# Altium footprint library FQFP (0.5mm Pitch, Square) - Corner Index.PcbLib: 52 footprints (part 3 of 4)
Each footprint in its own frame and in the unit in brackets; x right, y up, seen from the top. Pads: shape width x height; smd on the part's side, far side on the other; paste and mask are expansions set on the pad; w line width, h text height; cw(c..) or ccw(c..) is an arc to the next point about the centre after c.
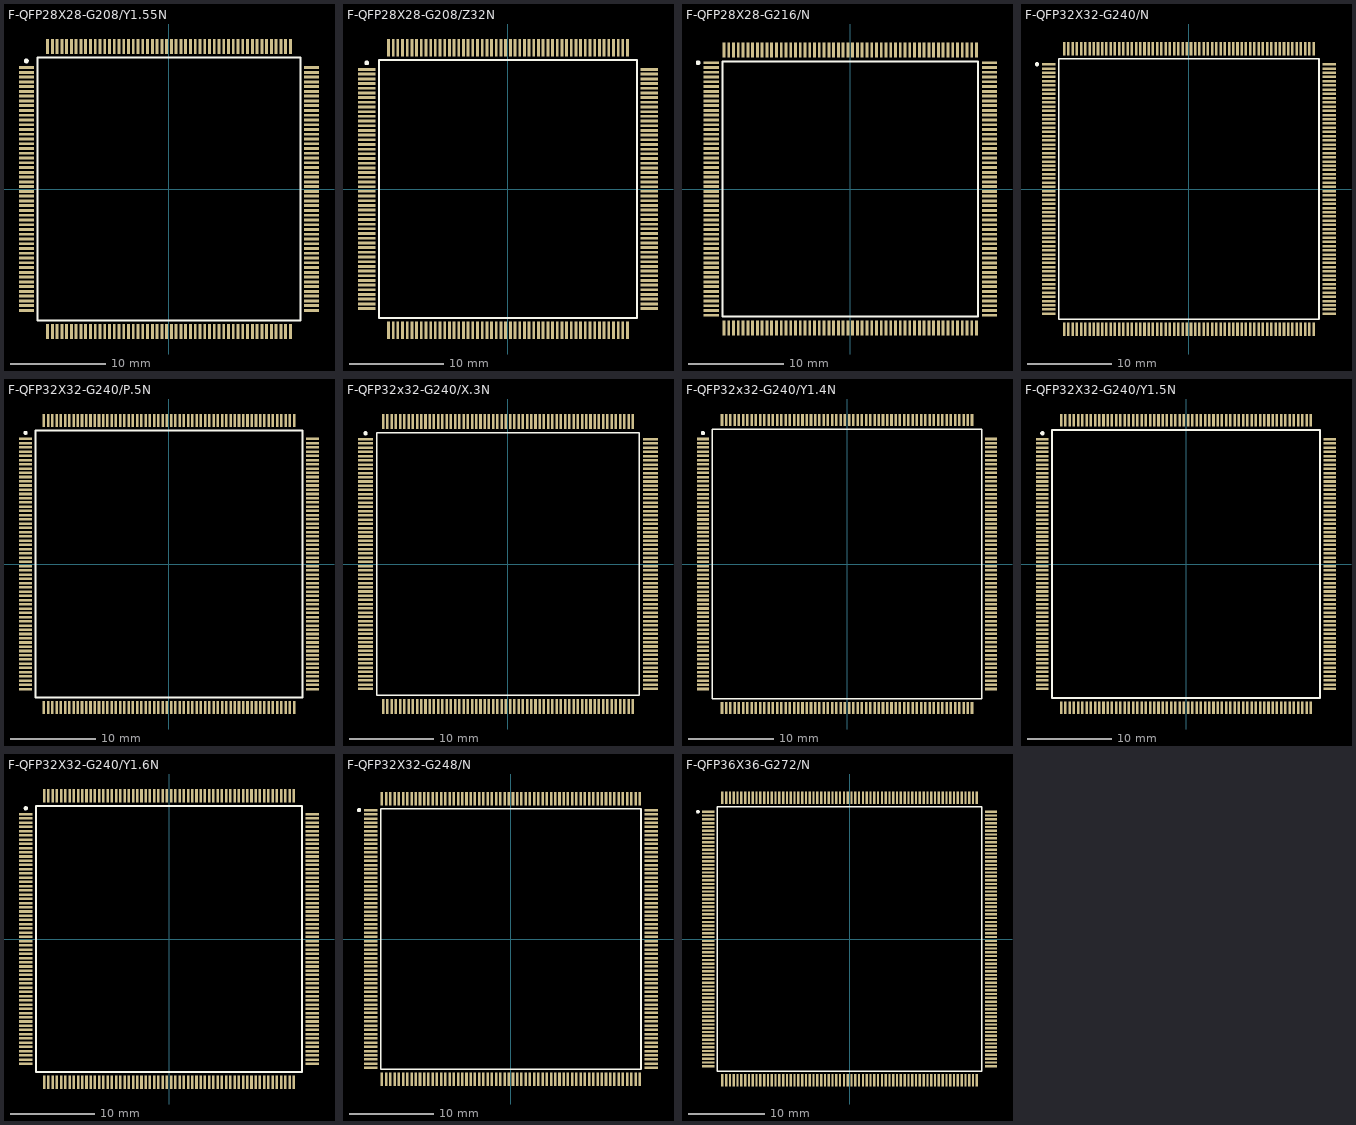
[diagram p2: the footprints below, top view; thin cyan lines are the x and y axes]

## F-QFP28X28-G208/Y1.55N [mm]
pads (208):
  rect 1.55x0.3 smd: 1(-14.975,12.75) 2(-14.975,12.25) 3(-14.975,11.75) 4(-14.975,11.25) 5(-14.975,10.75) 6(-14.975,10.25) 7(-14.975,9.75) 8(-14.975,9.25) 9(-14.975,8.75) 10(-14.975,8.25) 11(-14.975,7.75) 12(-14.975,7.25) 13(-14.975,6.75) 14(-14.975,6.25) 15(-14.975,5.75) 16(-14.975,5.25) 17(-14.975,4.75) 18(-14.975,4.25) 19(-14.975,3.75) 20(-14.975,3.25) 21(-14.975,2.75) 22(-14.975,2.25) 23(-14.975,1.75) 24(-14.975,1.25) 25(-14.975,0.75) 26(-14.975,0.25) 27(-14.975,-0.25) 28(-14.975,-0.75) 29(-14.975,-1.25) 30(-14.975,-1.75) 31(-14.975,-2.25) 32(-14.975,-2.75) 33(-14.975,-3.25) 34(-14.975,-3.75) 35(-14.975,-4.25) 36(-14.975,-4.75) 37(-14.975,-5.25) 38(-14.975,-5.75) 39(-14.975,-6.25) 40(-14.975,-6.75) 41(-14.975,-7.25) 42(-14.975,-7.75) 43(-14.975,-8.25) 44(-14.975,-8.75) 45(-14.975,-9.25) 46(-14.975,-9.75) 47(-14.975,-10.25) 48(-14.975,-10.75) 49(-14.975,-11.25) 50(-14.975,-11.75) 51(-14.975,-12.25) 52(-14.975,-12.75) 105(14.975,-12.75) 106(14.975,-12.25) 107(14.975,-11.75) 108(14.975,-11.25) 109(14.975,-10.75) 110(14.975,-10.25) 111(14.975,-9.75) 112(14.975,-9.25) 113(14.975,-8.75) 114(14.975,-8.25) 115(14.975,-7.75) 116(14.975,-7.25) 117(14.975,-6.75) 118(14.975,-6.25) 119(14.975,-5.75) 120(14.975,-5.25) 121(14.975,-4.75) 122(14.975,-4.25) 123(14.975,-3.75) 124(14.975,-3.25) 125(14.975,-2.75) 126(14.975,-2.25) 127(14.975,-1.75) 128(14.975,-1.25) 129(14.975,-0.75) 130(14.975,-0.25) 131(14.975,0.25) 132(14.975,0.75) 133(14.975,1.25) 134(14.975,1.75) 135(14.975,2.25) 136(14.975,2.75) 137(14.975,3.25) 138(14.975,3.75) 139(14.975,4.25) 140(14.975,4.75) 141(14.975,5.25) 142(14.975,5.75) 143(14.975,6.25) 144(14.975,6.75) 145(14.975,7.25) 146(14.975,7.75) 147(14.975,8.25) 148(14.975,8.75) 149(14.975,9.25) 150(14.975,9.75) 151(14.975,10.25) 152(14.975,10.75) 153(14.975,11.25) 154(14.975,11.75) 155(14.975,12.25) 156(14.975,12.75)
  rect 0.3x1.55 smd: 53(-12.75,-14.975) 54(-12.25,-14.975) 55(-11.75,-14.975) 56(-11.25,-14.975) 57(-10.75,-14.975) 58(-10.25,-14.975) 59(-9.75,-14.975) 60(-9.25,-14.975) 61(-8.75,-14.975) 62(-8.25,-14.975) 63(-7.75,-14.975) 64(-7.25,-14.975) 65(-6.75,-14.975) 66(-6.25,-14.975) 67(-5.75,-14.975) 68(-5.25,-14.975) 69(-4.75,-14.975) 70(-4.25,-14.975) 71(-3.75,-14.975) 72(-3.25,-14.975) 73(-2.75,-14.975) 74(-2.25,-14.975) 75(-1.75,-14.975) 76(-1.25,-14.975) 77(-0.75,-14.975) 78(-0.25,-14.975) 79(0.25,-14.975) 80(0.75,-14.975) 81(1.25,-14.975) 82(1.75,-14.975) 83(2.25,-14.975) 84(2.75,-14.975) 85(3.25,-14.975) 86(3.75,-14.975) 87(4.25,-14.975) 88(4.75,-14.975) 89(5.25,-14.975) 90(5.75,-14.975) 91(6.25,-14.975) 92(6.75,-14.975) 93(7.25,-14.975) 94(7.75,-14.975) 95(8.25,-14.975) 96(8.75,-14.975) 97(9.25,-14.975) 98(9.75,-14.975) 99(10.25,-14.975) 100(10.75,-14.975) 101(11.25,-14.975) 102(11.75,-14.975) 103(12.25,-14.975) 104(12.75,-14.975) 157(12.75,14.975) 158(12.25,14.975) 159(11.75,14.975) 160(11.25,14.975) 161(10.75,14.975) 162(10.25,14.975) 163(9.75,14.975) 164(9.25,14.975) 165(8.75,14.975) 166(8.25,14.975) 167(7.75,14.975) 168(7.25,14.975) 169(6.75,14.975) 170(6.25,14.975) 171(5.75,14.975) 172(5.25,14.975) 173(4.75,14.975) 174(4.25,14.975) 175(3.75,14.975) 176(3.25,14.975) 177(2.75,14.975) 178(2.25,14.975) 179(1.75,14.975) 180(1.25,14.975) 181(0.75,14.975) 182(0.25,14.975) 183(-0.25,14.975) 184(-0.75,14.975) 185(-1.25,14.975) 186(-1.75,14.975) 187(-2.25,14.975) 188(-2.75,14.975) 189(-3.25,14.975) 190(-3.75,14.975) 191(-4.25,14.975) 192(-4.75,14.975) 193(-5.25,14.975) 194(-5.75,14.975) 195(-6.25,14.975) 196(-6.75,14.975) 197(-7.25,14.975) 198(-7.75,14.975) 199(-8.25,14.975) 200(-8.75,14.975) 201(-9.25,14.975) 202(-9.75,14.975) 203(-10.25,14.975) 204(-10.75,14.975) 205(-11.25,14.975) 206(-11.75,14.975) 207(-12.25,14.975) 208(-12.75,14.975)
Top Overlay:
  circle w0.25: c-14.975,13.45 r0.125
  lines w0.2: -13.8,-13.8 -13.8,13.8 13.8,13.8 13.8,-13.8 -13.8,-13.8

## F-QFP28X28-G208/Z32N [mm]
pads (208):
  rect 1.85x0.3 smd: 1(-15.075,12.75) 2(-15.075,12.25) 3(-15.075,11.75) 4(-15.075,11.25) 5(-15.075,10.75) 6(-15.075,10.25) 7(-15.075,9.75) 8(-15.075,9.25) 9(-15.075,8.75) 10(-15.075,8.25) 11(-15.075,7.75) 12(-15.075,7.25) 13(-15.075,6.75) 14(-15.075,6.25) 15(-15.075,5.75) 16(-15.075,5.25) 17(-15.075,4.75) 18(-15.075,4.25) 19(-15.075,3.75) 20(-15.075,3.25) 21(-15.075,2.75) 22(-15.075,2.25) 23(-15.075,1.75) 24(-15.075,1.25) 25(-15.075,0.75) 26(-15.075,0.25) 27(-15.075,-0.25) 28(-15.075,-0.75) 29(-15.075,-1.25) 30(-15.075,-1.75) 31(-15.075,-2.25) 32(-15.075,-2.75) 33(-15.075,-3.25) 34(-15.075,-3.75) 35(-15.075,-4.25) 36(-15.075,-4.75) 37(-15.075,-5.25) 38(-15.075,-5.75) 39(-15.075,-6.25) 40(-15.075,-6.75) 41(-15.075,-7.25) 42(-15.075,-7.75) 43(-15.075,-8.25) 44(-15.075,-8.75) 45(-15.075,-9.25) 46(-15.075,-9.75) 47(-15.075,-10.25) 48(-15.075,-10.75) 49(-15.075,-11.25) 50(-15.075,-11.75) 51(-15.075,-12.25) 52(-15.075,-12.75) 105(15.075,-12.75) 106(15.075,-12.25) 107(15.075,-11.75) 108(15.075,-11.25) 109(15.075,-10.75) 110(15.075,-10.25) 111(15.075,-9.75) 112(15.075,-9.25) 113(15.075,-8.75) 114(15.075,-8.25) 115(15.075,-7.75) 116(15.075,-7.25) 117(15.075,-6.75) 118(15.075,-6.25) 119(15.075,-5.75) 120(15.075,-5.25) 121(15.075,-4.75) 122(15.075,-4.25) 123(15.075,-3.75) 124(15.075,-3.25) 125(15.075,-2.75) 126(15.075,-2.25) 127(15.075,-1.75) 128(15.075,-1.25) 129(15.075,-0.75) 130(15.075,-0.25) 131(15.075,0.25) 132(15.075,0.75) 133(15.075,1.25) 134(15.075,1.75) 135(15.075,2.25) 136(15.075,2.75) 137(15.075,3.25) 138(15.075,3.75) 139(15.075,4.25) 140(15.075,4.75) 141(15.075,5.25) 142(15.075,5.75) 143(15.075,6.25) 144(15.075,6.75) 145(15.075,7.25) 146(15.075,7.75) 147(15.075,8.25) 148(15.075,8.75) 149(15.075,9.25) 150(15.075,9.75) 151(15.075,10.25) 152(15.075,10.75) 153(15.075,11.25) 154(15.075,11.75) 155(15.075,12.25) 156(15.075,12.75)
  rect 0.3x1.85 smd: 53(-12.75,-15.075) 54(-12.25,-15.075) 55(-11.75,-15.075) 56(-11.25,-15.075) 57(-10.75,-15.075) 58(-10.25,-15.075) 59(-9.75,-15.075) 60(-9.25,-15.075) 61(-8.75,-15.075) 62(-8.25,-15.075) 63(-7.75,-15.075) 64(-7.25,-15.075) 65(-6.75,-15.075) 66(-6.25,-15.075) 67(-5.75,-15.075) 68(-5.25,-15.075) 69(-4.75,-15.075) 70(-4.25,-15.075) 71(-3.75,-15.075) 72(-3.25,-15.075) 73(-2.75,-15.075) 74(-2.25,-15.075) 75(-1.75,-15.075) 76(-1.25,-15.075) 77(-0.75,-15.075) 78(-0.25,-15.075) 79(0.25,-15.075) 80(0.75,-15.075) 81(1.25,-15.075) 82(1.75,-15.075) 83(2.25,-15.075) 84(2.75,-15.075) 85(3.25,-15.075) 86(3.75,-15.075) 87(4.25,-15.075) 88(4.75,-15.075) 89(5.25,-15.075) 90(5.75,-15.075) 91(6.25,-15.075) 92(6.75,-15.075) 93(7.25,-15.075) 94(7.75,-15.075) 95(8.25,-15.075) 96(8.75,-15.075) 97(9.25,-15.075) 98(9.75,-15.075) 99(10.25,-15.075) 100(10.75,-15.075) 101(11.25,-15.075) 102(11.75,-15.075) 103(12.25,-15.075) 104(12.75,-15.075) 157(12.75,15.075) 158(12.25,15.075) 159(11.75,15.075) 160(11.25,15.075) 161(10.75,15.075) 162(10.25,15.075) 163(9.75,15.075) 164(9.25,15.075) 165(8.75,15.075) 166(8.25,15.075) 167(7.75,15.075) 168(7.25,15.075) 169(6.75,15.075) 170(6.25,15.075) 171(5.75,15.075) 172(5.25,15.075) 173(4.75,15.075) 174(4.25,15.075) 175(3.75,15.075) 176(3.25,15.075) 177(2.75,15.075) 178(2.25,15.075) 179(1.75,15.075) 180(1.25,15.075) 181(0.75,15.075) 182(0.25,15.075) 183(-0.25,15.075) 184(-0.75,15.075) 185(-1.25,15.075) 186(-1.75,15.075) 187(-2.25,15.075) 188(-2.75,15.075) 189(-3.25,15.075) 190(-3.75,15.075) 191(-4.25,15.075) 192(-4.75,15.075) 193(-5.25,15.075) 194(-5.75,15.075) 195(-6.25,15.075) 196(-6.75,15.075) 197(-7.25,15.075) 198(-7.75,15.075) 199(-8.25,15.075) 200(-8.75,15.075) 201(-9.25,15.075) 202(-9.75,15.075) 203(-10.25,15.075) 204(-10.75,15.075) 205(-11.25,15.075) 206(-11.75,15.075) 207(-12.25,15.075) 208(-12.75,15.075)
Top Overlay:
  circle w0.25: c-15.075,13.45 r0.125
  lines w0.2: -13.75,-13.75 13.75,-13.75 13.75,13.75 -13.75,13.75 -13.75,-13.75

## F-QFP28X28-G216/N [mm]
pads (216):
  rect 1.6x0.3 smd: 1(-14.6,13.25) 2(-14.6,12.75) 3(-14.6,12.25) 4(-14.6,11.75) 5(-14.6,11.25) 6(-14.6,10.75) 7(-14.6,10.25) 8(-14.6,9.75) 9(-14.6,9.25) 10(-14.6,8.75) 11(-14.6,8.25) 12(-14.6,7.75) 13(-14.6,7.25) 14(-14.6,6.75) 15(-14.6,6.25) 16(-14.6,5.75) 17(-14.6,5.25) 18(-14.6,4.75) 19(-14.6,4.25) 20(-14.6,3.75) 21(-14.6,3.25) 22(-14.6,2.75) 23(-14.6,2.25) 24(-14.6,1.75) 25(-14.6,1.25) 26(-14.6,0.75) 27(-14.6,0.25) 28(-14.6,-0.25) 29(-14.6,-0.75) 30(-14.6,-1.25) 31(-14.6,-1.75) 32(-14.6,-2.25) 33(-14.6,-2.75) 34(-14.6,-3.25) 35(-14.6,-3.75) 36(-14.6,-4.25) 37(-14.6,-4.75) 38(-14.6,-5.25) 39(-14.6,-5.75) 40(-14.6,-6.25) 41(-14.6,-6.75) 42(-14.6,-7.25) 43(-14.6,-7.75) 44(-14.6,-8.25) 45(-14.6,-8.75) 46(-14.6,-9.25) 47(-14.6,-9.75) 48(-14.6,-10.25) 49(-14.6,-10.75) 50(-14.6,-11.25) 51(-14.6,-11.75) 52(-14.6,-12.25) 53(-14.6,-12.75) 54(-14.6,-13.25) 109(14.6,-13.25) 110(14.6,-12.75) 111(14.6,-12.25) 112(14.6,-11.75) 113(14.6,-11.25) 114(14.6,-10.75) 115(14.6,-10.25) 116(14.6,-9.75) 117(14.6,-9.25) 118(14.6,-8.75) 119(14.6,-8.25) 120(14.6,-7.75) 121(14.6,-7.25) 122(14.6,-6.75) 123(14.6,-6.25) 124(14.6,-5.75) 125(14.6,-5.25) 126(14.6,-4.75) 127(14.6,-4.25) 128(14.6,-3.75) 129(14.6,-3.25) 130(14.6,-2.75) 131(14.6,-2.25) 132(14.6,-1.75) 133(14.6,-1.25) 134(14.6,-0.75) 135(14.6,-0.25) 136(14.6,0.25) 137(14.6,0.75) 138(14.6,1.25) 139(14.6,1.75) 140(14.6,2.25) 141(14.6,2.75) 142(14.6,3.25) 143(14.6,3.75) 144(14.6,4.25) 145(14.6,4.75) 146(14.6,5.25) 147(14.6,5.75) 148(14.6,6.25) 149(14.6,6.75) 150(14.6,7.25) 151(14.6,7.75) 152(14.6,8.25) 153(14.6,8.75) 154(14.6,9.25) 155(14.6,9.75) 156(14.6,10.25) 157(14.6,10.75) 158(14.6,11.25) 159(14.6,11.75) 160(14.6,12.25) 161(14.6,12.75) 162(14.6,13.25)
  rect 0.3x1.6 smd: 55(-13.25,-14.6) 56(-12.75,-14.6) 57(-12.25,-14.6) 58(-11.75,-14.6) 59(-11.25,-14.6) 60(-10.75,-14.6) 61(-10.25,-14.6) 62(-9.75,-14.6) 63(-9.25,-14.6) 64(-8.75,-14.6) 65(-8.25,-14.6) 66(-7.75,-14.6) 67(-7.25,-14.6) 68(-6.75,-14.6) 69(-6.25,-14.6) 70(-5.75,-14.6) 71(-5.25,-14.6) 72(-4.75,-14.6) 73(-4.25,-14.6) 74(-3.75,-14.6) 75(-3.25,-14.6) 76(-2.75,-14.6) 77(-2.25,-14.6) 78(-1.75,-14.6) 79(-1.25,-14.6) 80(-0.75,-14.6) 81(-0.25,-14.6) 82(0.25,-14.6) 83(0.75,-14.6) 84(1.25,-14.6) 85(1.75,-14.6) 86(2.25,-14.6) 87(2.75,-14.6) 88(3.25,-14.6) 89(3.75,-14.6) 90(4.25,-14.6) 91(4.75,-14.6) 92(5.25,-14.6) 93(5.75,-14.6) 94(6.25,-14.6) 95(6.75,-14.6) 96(7.25,-14.6) 97(7.75,-14.6) 98(8.25,-14.6) 99(8.75,-14.6) 100(9.25,-14.6) 101(9.75,-14.6) 102(10.25,-14.6) 103(10.75,-14.6) 104(11.25,-14.6) 105(11.75,-14.6) 106(12.25,-14.6) 107(12.75,-14.6) 108(13.25,-14.6) 163(13.25,14.6) 164(12.75,14.6) 165(12.25,14.6) 166(11.75,14.6) 167(11.25,14.6) 168(10.75,14.6) 169(10.25,14.6) 170(9.75,14.6) 171(9.25,14.6) 172(8.75,14.6) 173(8.25,14.6) 174(7.75,14.6) 175(7.25,14.6) 176(6.75,14.6) 177(6.25,14.6) 178(5.75,14.6) 179(5.25,14.6) 180(4.75,14.6) 181(4.25,14.6) 182(3.75,14.6) 183(3.25,14.6) 184(2.75,14.6) 185(2.25,14.6) 186(1.75,14.6) 187(1.25,14.6) 188(0.75,14.6) 189(0.25,14.6) 190(-0.25,14.6) 191(-0.75,14.6) 192(-1.25,14.6) 193(-1.75,14.6) 194(-2.25,14.6) 195(-2.75,14.6) 196(-3.25,14.6) 197(-3.75,14.6) 198(-4.25,14.6) 199(-4.75,14.6) 200(-5.25,14.6) 201(-5.75,14.6) 202(-6.25,14.6) 203(-6.75,14.6) 204(-7.25,14.6) 205(-7.75,14.6) 206(-8.25,14.6) 207(-8.75,14.6) 208(-9.25,14.6) 209(-9.75,14.6) 210(-10.25,14.6) 211(-10.75,14.6) 212(-11.25,14.6) 213(-11.75,14.6) 214(-12.25,14.6) 215(-12.75,14.6) 216(-13.25,14.6)
Top Overlay:
  circle w0.25: c-15.96,13.25 r0.125
  lines w0.2: -13.4,-13.4 13.4,-13.4 13.4,13.4 -13.4,13.4 -13.4,-13.4

## F-QFP32X32-G240/N [mm]
pads (240):
  rect 1.6x0.3 smd: 1(-16.6,14.75) 2(-16.6,14.25) 3(-16.6,13.75) 4(-16.6,13.25) 5(-16.6,12.75) 6(-16.6,12.25) 7(-16.6,11.75) 8(-16.6,11.25) 9(-16.6,10.75) 10(-16.6,10.25) 11(-16.6,9.75) 12(-16.6,9.25) 13(-16.6,8.75) 14(-16.6,8.25) 15(-16.6,7.75) 16(-16.6,7.25) 17(-16.6,6.75) 18(-16.6,6.25) 19(-16.6,5.75) 20(-16.6,5.25) 21(-16.6,4.75) 22(-16.6,4.25) 23(-16.6,3.75) 24(-16.6,3.25) 25(-16.6,2.75) 26(-16.6,2.25) 27(-16.6,1.75) 28(-16.6,1.25) 29(-16.6,0.75) 30(-16.6,0.25) 31(-16.6,-0.25) 32(-16.6,-0.75) 33(-16.6,-1.25) 34(-16.6,-1.75) 35(-16.6,-2.25) 36(-16.6,-2.75) 37(-16.6,-3.25) 38(-16.6,-3.75) 39(-16.6,-4.25) 40(-16.6,-4.75) 41(-16.6,-5.25) 42(-16.6,-5.75) 43(-16.6,-6.25) 44(-16.6,-6.75) 45(-16.6,-7.25) 46(-16.6,-7.75) 47(-16.6,-8.25) 48(-16.6,-8.75) 49(-16.6,-9.25) 50(-16.6,-9.75) 51(-16.6,-10.25) 52(-16.6,-10.75) 53(-16.6,-11.25) 54(-16.6,-11.75) 55(-16.6,-12.25) 56(-16.6,-12.75) 57(-16.6,-13.25) 58(-16.6,-13.75) 59(-16.6,-14.25) 60(-16.6,-14.75) 121(16.6,-14.75) 122(16.6,-14.25) 123(16.6,-13.75) 124(16.6,-13.25) 125(16.6,-12.75) 126(16.6,-12.25) 127(16.6,-11.75) 128(16.6,-11.25) 129(16.6,-10.75) 130(16.6,-10.25) 131(16.6,-9.75) 132(16.6,-9.25) 133(16.6,-8.75) 134(16.6,-8.25) 135(16.6,-7.75) 136(16.6,-7.25) 137(16.6,-6.75) 138(16.6,-6.25) 139(16.6,-5.75) 140(16.6,-5.25) 141(16.6,-4.75) 142(16.6,-4.25) 143(16.6,-3.75) 144(16.6,-3.25) 145(16.6,-2.75) 146(16.6,-2.25) 147(16.6,-1.75) 148(16.6,-1.25) 149(16.6,-0.75) 150(16.6,-0.25) 151(16.6,0.25) 152(16.6,0.75) 153(16.6,1.25) 154(16.6,1.75) 155(16.6,2.25) 156(16.6,2.75) 157(16.6,3.25) 158(16.6,3.75) 159(16.6,4.25) 160(16.6,4.75) 161(16.6,5.25) 162(16.6,5.75) 163(16.6,6.25) 164(16.6,6.75) 165(16.6,7.25) 166(16.6,7.75) 167(16.6,8.25) 168(16.6,8.75) 169(16.6,9.25) 170(16.6,9.75) 171(16.6,10.25) 172(16.6,10.75) 173(16.6,11.25) 174(16.6,11.75) 175(16.6,12.25) 176(16.6,12.75) 177(16.6,13.25) 178(16.6,13.75) 179(16.6,14.25) 180(16.6,14.75)
  rect 0.3x1.6 smd: 61(-14.75,-16.6) 62(-14.25,-16.6) 63(-13.75,-16.6) 64(-13.25,-16.6) 65(-12.75,-16.6) 66(-12.25,-16.6) 67(-11.75,-16.6) 68(-11.25,-16.6) 69(-10.75,-16.6) 70(-10.25,-16.6) 71(-9.75,-16.6) 72(-9.25,-16.6) 73(-8.75,-16.6) 74(-8.25,-16.6) 75(-7.75,-16.6) 76(-7.25,-16.6) 77(-6.75,-16.6) 78(-6.25,-16.6) 79(-5.75,-16.6) 80(-5.25,-16.6) 81(-4.75,-16.6) 82(-4.25,-16.6) 83(-3.75,-16.6) 84(-3.25,-16.6) 85(-2.75,-16.6) 86(-2.25,-16.6) 87(-1.75,-16.6) 88(-1.25,-16.6) 89(-0.75,-16.6) 90(-0.25,-16.6) 91(0.25,-16.6) 92(0.75,-16.6) 93(1.25,-16.6) 94(1.75,-16.6) 95(2.25,-16.6) 96(2.75,-16.6) 97(3.25,-16.6) 98(3.75,-16.6) 99(4.25,-16.6) 100(4.75,-16.6) 101(5.25,-16.6) 102(5.75,-16.6) 103(6.25,-16.6) 104(6.75,-16.6) 105(7.25,-16.6) 106(7.75,-16.6) 107(8.25,-16.6) 108(8.75,-16.6) 109(9.25,-16.6) 110(9.75,-16.6) 111(10.25,-16.6) 112(10.75,-16.6) 113(11.25,-16.6) 114(11.75,-16.6) 115(12.25,-16.6) 116(12.75,-16.6) 117(13.25,-16.6) 118(13.75,-16.6) 119(14.25,-16.6) 120(14.75,-16.6) 181(14.75,16.6) 182(14.25,16.6) 183(13.75,16.6) 184(13.25,16.6) 185(12.75,16.6) 186(12.25,16.6) 187(11.75,16.6) 188(11.25,16.6) 189(10.75,16.6) 190(10.25,16.6) 191(9.75,16.6) 192(9.25,16.6) 193(8.75,16.6) 194(8.25,16.6) 195(7.75,16.6) 196(7.25,16.6) 197(6.75,16.6) 198(6.25,16.6) 199(5.75,16.6) 200(5.25,16.6) 201(4.75,16.6) 202(4.25,16.6) 203(3.75,16.6) 204(3.25,16.6) 205(2.75,16.6) 206(2.25,16.6) 207(1.75,16.6) 208(1.25,16.6) 209(0.75,16.6) 210(0.25,16.6) 211(-0.25,16.6) 212(-0.75,16.6) 213(-1.25,16.6) 214(-1.75,16.6) 215(-2.25,16.6) 216(-2.75,16.6) 217(-3.25,16.6) 218(-3.75,16.6) 219(-4.25,16.6) 220(-4.75,16.6) 221(-5.25,16.6) 222(-5.75,16.6) 223(-6.25,16.6) 224(-6.75,16.6) 225(-7.25,16.6) 226(-7.75,16.6) 227(-8.25,16.6) 228(-8.75,16.6) 229(-9.25,16.6) 230(-9.75,16.6) 231(-10.25,16.6) 232(-10.75,16.6) 233(-11.25,16.6) 234(-11.75,16.6) 235(-12.25,16.6) 236(-12.75,16.6) 237(-13.25,16.6) 238(-13.75,16.6) 239(-14.25,16.6) 240(-14.75,16.6)
Top Overlay:
  circle w0.25: c-17.96,14.75 r0.125
  lines w0.2: -15.4,-15.4 -15.4,15.4 15.4,15.4 15.4,-15.4 -15.4,-15.4

## F-QFP32X32-G240/P.5N [mm]
pads (240):
  rect 1.55x0.3 smd: 1(-16.9,14.75) 2(-16.9,14.25) 3(-16.9,13.75) 4(-16.9,13.25) 5(-16.9,12.75) 6(-16.9,12.25) 7(-16.9,11.75) 8(-16.9,11.25) 9(-16.9,10.75) 10(-16.9,10.25) 11(-16.9,9.75) 12(-16.9,9.25) 13(-16.9,8.75) 14(-16.9,8.25) 15(-16.9,7.75) 16(-16.9,7.25) 17(-16.9,6.75) 18(-16.9,6.25) 19(-16.9,5.75) 20(-16.9,5.25) 21(-16.9,4.75) 22(-16.9,4.25) 23(-16.9,3.75) 24(-16.9,3.25) 25(-16.9,2.75) 26(-16.9,2.25) 27(-16.9,1.75) 28(-16.9,1.25) 29(-16.9,0.75) 30(-16.9,0.25) 31(-16.9,-0.25) 32(-16.9,-0.75) 33(-16.9,-1.25) 34(-16.9,-1.75) 35(-16.9,-2.25) 36(-16.9,-2.75) 37(-16.9,-3.25) 38(-16.9,-3.75) 39(-16.9,-4.25) 40(-16.9,-4.75) 41(-16.9,-5.25) 42(-16.9,-5.75) 43(-16.9,-6.25) 44(-16.9,-6.75) 45(-16.9,-7.25) 46(-16.9,-7.75) 47(-16.9,-8.25) 48(-16.9,-8.75) 49(-16.9,-9.25) 50(-16.9,-9.75) 51(-16.9,-10.25) 52(-16.9,-10.75) 53(-16.9,-11.25) 54(-16.9,-11.75) 55(-16.9,-12.25) 56(-16.9,-12.75) 57(-16.9,-13.25) 58(-16.9,-13.75) 59(-16.9,-14.25) 60(-16.9,-14.75) 121(16.9,-14.75) 122(16.9,-14.25) 123(16.9,-13.75) 124(16.9,-13.25) 125(16.9,-12.75) 126(16.9,-12.25) 127(16.9,-11.75) 128(16.9,-11.25) 129(16.9,-10.75) 130(16.9,-10.25) 131(16.9,-9.75) 132(16.9,-9.25) 133(16.9,-8.75) 134(16.9,-8.25) 135(16.9,-7.75) 136(16.9,-7.25) 137(16.9,-6.75) 138(16.9,-6.25) 139(16.9,-5.75) 140(16.9,-5.25) 141(16.9,-4.75) 142(16.9,-4.25) 143(16.9,-3.75) 144(16.9,-3.25) 145(16.9,-2.75) 146(16.9,-2.25) 147(16.9,-1.75) 148(16.9,-1.25) 149(16.9,-0.75) 150(16.9,-0.25) 151(16.9,0.25) 152(16.9,0.75) 153(16.9,1.25) 154(16.9,1.75) 155(16.9,2.25) 156(16.9,2.75) 157(16.9,3.25) 158(16.9,3.75) 159(16.9,4.25) 160(16.9,4.75) 161(16.9,5.25) 162(16.9,5.75) 163(16.9,6.25) 164(16.9,6.75) 165(16.9,7.25) 166(16.9,7.75) 167(16.9,8.25) 168(16.9,8.75) 169(16.9,9.25) 170(16.9,9.75) 171(16.9,10.25) 172(16.9,10.75) 173(16.9,11.25) 174(16.9,11.75) 175(16.9,12.25) 176(16.9,12.75) 177(16.9,13.25) 178(16.9,13.75) 179(16.9,14.25) 180(16.9,14.75)
  rect 0.3x1.55 smd: 61(-14.75,-16.9) 62(-14.25,-16.9) 63(-13.75,-16.9) 64(-13.25,-16.9) 65(-12.75,-16.9) 66(-12.25,-16.9) 67(-11.75,-16.9) 68(-11.25,-16.9) 69(-10.75,-16.9) 70(-10.25,-16.9) 71(-9.75,-16.9) 72(-9.25,-16.9) 73(-8.75,-16.9) 74(-8.25,-16.9) 75(-7.75,-16.9) 76(-7.25,-16.9) 77(-6.75,-16.9) 78(-6.25,-16.9) 79(-5.75,-16.9) 80(-5.25,-16.9) 81(-4.75,-16.9) 82(-4.25,-16.9) 83(-3.75,-16.9) 84(-3.25,-16.9) 85(-2.75,-16.9) 86(-2.25,-16.9) 87(-1.75,-16.9) 88(-1.25,-16.9) 89(-0.75,-16.9) 90(-0.25,-16.9) 91(0.25,-16.9) 92(0.75,-16.9) 93(1.25,-16.9) 94(1.75,-16.9) 95(2.25,-16.9) 96(2.75,-16.9) 97(3.25,-16.9) 98(3.75,-16.9) 99(4.25,-16.9) 100(4.75,-16.9) 101(5.25,-16.9) 102(5.75,-16.9) 103(6.25,-16.9) 104(6.75,-16.9) 105(7.25,-16.9) 106(7.75,-16.9) 107(8.25,-16.9) 108(8.75,-16.9) 109(9.25,-16.9) 110(9.75,-16.9) 111(10.25,-16.9) 112(10.75,-16.9) 113(11.25,-16.9) 114(11.75,-16.9) 115(12.25,-16.9) 116(12.75,-16.9) 117(13.25,-16.9) 118(13.75,-16.9) 119(14.25,-16.9) 120(14.75,-16.9) 181(14.75,16.9) 182(14.25,16.9) 183(13.75,16.9) 184(13.25,16.9) 185(12.75,16.9) 186(12.25,16.9) 187(11.75,16.9) 188(11.25,16.9) 189(10.75,16.9) 190(10.25,16.9) 191(9.75,16.9) 192(9.25,16.9) 193(8.75,16.9) 194(8.25,16.9) 195(7.75,16.9) 196(7.25,16.9) 197(6.75,16.9) 198(6.25,16.9) 199(5.75,16.9) 200(5.25,16.9) 201(4.75,16.9) 202(4.25,16.9) 203(3.75,16.9) 204(3.25,16.9) 205(2.75,16.9) 206(2.25,16.9) 207(1.75,16.9) 208(1.25,16.9) 209(0.75,16.9) 210(0.25,16.9) 211(-0.25,16.9) 212(-0.75,16.9) 213(-1.25,16.9) 214(-1.75,16.9) 215(-2.25,16.9) 216(-2.75,16.9) 217(-3.25,16.9) 218(-3.75,16.9) 219(-4.25,16.9) 220(-4.75,16.9) 221(-5.25,16.9) 222(-5.75,16.9) 223(-6.25,16.9) 224(-6.75,16.9) 225(-7.25,16.9) 226(-7.75,16.9) 227(-8.25,16.9) 228(-8.75,16.9) 229(-9.25,16.9) 230(-9.75,16.9) 231(-10.25,16.9) 232(-10.75,16.9) 233(-11.25,16.9) 234(-11.75,16.9) 235(-12.25,16.9) 236(-12.75,16.9) 237(-13.25,16.9) 238(-13.75,16.9) 239(-14.25,16.9) 240(-14.75,16.9)
Top Overlay:
  circle w0.25: c-16.9,15.45 r0.125
  lines w0.2: -15.725,-15.725 -15.725,15.725 15.725,15.725 15.725,-15.725 -15.725,-15.725

## F-QFP32x32-G240/X.3N [mm]
pads (240):
  rect 1.8x0.3 smd: 1(-16.83,14.75) 2(-16.83,14.25) 3(-16.83,13.75) 4(-16.83,13.25) 5(-16.83,12.75) 6(-16.83,12.25) 7(-16.83,11.75) 8(-16.83,11.25) 9(-16.83,10.75) 10(-16.83,10.25) 11(-16.83,9.75) 12(-16.83,9.25) 13(-16.83,8.75) 14(-16.83,8.25) 15(-16.83,7.75) 16(-16.83,7.25) 17(-16.83,6.75) 18(-16.83,6.25) 19(-16.83,5.75) 20(-16.83,5.25) 21(-16.83,4.75) 22(-16.83,4.25) 23(-16.83,3.75) 24(-16.83,3.25) 25(-16.83,2.75) 26(-16.83,2.25) 27(-16.83,1.75) 28(-16.83,1.25) 29(-16.83,0.75) 30(-16.83,0.25) 31(-16.83,-0.25) 32(-16.83,-0.75) 33(-16.83,-1.25) 34(-16.83,-1.75) 35(-16.83,-2.25) 36(-16.83,-2.75) 37(-16.83,-3.25) 38(-16.83,-3.75) 39(-16.83,-4.25) 40(-16.83,-4.75) 41(-16.83,-5.25) 42(-16.83,-5.75) 43(-16.83,-6.25) 44(-16.83,-6.75) 45(-16.83,-7.25) 46(-16.83,-7.75) 47(-16.83,-8.25) 48(-16.83,-8.75) 49(-16.83,-9.25) 50(-16.83,-9.75) 51(-16.83,-10.25) 52(-16.83,-10.75) 53(-16.83,-11.25) 54(-16.83,-11.75) 55(-16.83,-12.25) 56(-16.83,-12.75) 57(-16.83,-13.25) 58(-16.83,-13.75) 59(-16.83,-14.25) 60(-16.83,-14.75) 121(16.83,-14.75) 122(16.83,-14.25) 123(16.83,-13.75) 124(16.83,-13.25) 125(16.83,-12.75) 126(16.83,-12.25) 127(16.83,-11.75) 128(16.83,-11.25) 129(16.83,-10.75) 130(16.83,-10.25) 131(16.83,-9.75) 132(16.83,-9.25) 133(16.83,-8.75) 134(16.83,-8.25) 135(16.83,-7.75) 136(16.83,-7.25) 137(16.83,-6.75) 138(16.83,-6.25) 139(16.83,-5.75) 140(16.83,-5.25) 141(16.83,-4.75) 142(16.83,-4.25) 143(16.83,-3.75) 144(16.83,-3.25) 145(16.83,-2.75) 146(16.83,-2.25) 147(16.83,-1.75) 148(16.83,-1.25) 149(16.83,-0.75) 150(16.83,-0.25) 151(16.83,0.25) 152(16.83,0.75) 153(16.83,1.25) 154(16.83,1.75) 155(16.83,2.25) 156(16.83,2.75) 157(16.83,3.25) 158(16.83,3.75) 159(16.83,4.25) 160(16.83,4.75) 161(16.83,5.25) 162(16.83,5.75) 163(16.83,6.25) 164(16.83,6.75) 165(16.83,7.25) 166(16.83,7.75) 167(16.83,8.25) 168(16.83,8.75) 169(16.83,9.25) 170(16.83,9.75) 171(16.83,10.25) 172(16.83,10.75) 173(16.83,11.25) 174(16.83,11.75) 175(16.83,12.25) 176(16.83,12.75) 177(16.83,13.25) 178(16.83,13.75) 179(16.83,14.25) 180(16.83,14.75)
  rect 0.3x1.8 smd: 61(-14.75,-16.83) 62(-14.25,-16.83) 63(-13.75,-16.83) 64(-13.25,-16.83) 65(-12.75,-16.83) 66(-12.25,-16.83) 67(-11.75,-16.83) 68(-11.25,-16.83) 69(-10.75,-16.83) 70(-10.25,-16.83) 71(-9.75,-16.83) 72(-9.25,-16.83) 73(-8.75,-16.83) 74(-8.25,-16.83) 75(-7.75,-16.83) 76(-7.25,-16.83) 77(-6.75,-16.83) 78(-6.25,-16.83) 79(-5.75,-16.83) 80(-5.25,-16.83) 81(-4.75,-16.83) 82(-4.25,-16.83) 83(-3.75,-16.83) 84(-3.25,-16.83) 85(-2.75,-16.83) 86(-2.25,-16.83) 87(-1.75,-16.83) 88(-1.25,-16.83) 89(-0.75,-16.83) 90(-0.25,-16.83) 91(0.25,-16.83) 92(0.75,-16.83) 93(1.25,-16.83) 94(1.75,-16.83) 95(2.25,-16.83) 96(2.75,-16.83) 97(3.25,-16.83) 98(3.75,-16.83) 99(4.25,-16.83) 100(4.75,-16.83) 101(5.25,-16.83) 102(5.75,-16.83) 103(6.25,-16.83) 104(6.75,-16.83) 105(7.25,-16.83) 106(7.75,-16.83) 107(8.25,-16.83) 108(8.75,-16.83) 109(9.25,-16.83) 110(9.75,-16.83) 111(10.25,-16.83) 112(10.75,-16.83) 113(11.25,-16.83) 114(11.75,-16.83) 115(12.25,-16.83) 116(12.75,-16.83) 117(13.25,-16.83) 118(13.75,-16.83) 119(14.25,-16.83) 120(14.75,-16.83) 181(14.75,16.83) 182(14.25,16.83) 183(13.75,16.83) 184(13.25,16.83) 185(12.75,16.83) 186(12.25,16.83) 187(11.75,16.83) 188(11.25,16.83) 189(10.75,16.83) 190(10.25,16.83) 191(9.75,16.83) 192(9.25,16.83) 193(8.75,16.83) 194(8.25,16.83) 195(7.75,16.83) 196(7.25,16.83) 197(6.75,16.83) 198(6.25,16.83) 199(5.75,16.83) 200(5.25,16.83) 201(4.75,16.83) 202(4.25,16.83) 203(3.75,16.83) 204(3.25,16.83) 205(2.75,16.83) 206(2.25,16.83) 207(1.75,16.83) 208(1.25,16.83) 209(0.75,16.83) 210(0.25,16.83) 211(-0.25,16.83) 212(-0.75,16.83) 213(-1.25,16.83) 214(-1.75,16.83) 215(-2.25,16.83) 216(-2.75,16.83) 217(-3.25,16.83) 218(-3.75,16.83) 219(-4.25,16.83) 220(-4.75,16.83) 221(-5.25,16.83) 222(-5.75,16.83) 223(-6.25,16.83) 224(-6.75,16.83) 225(-7.25,16.83) 226(-7.75,16.83) 227(-8.25,16.83) 228(-8.75,16.83) 229(-9.25,16.83) 230(-9.75,16.83) 231(-10.25,16.83) 232(-10.75,16.83) 233(-11.25,16.83) 234(-11.75,16.83) 235(-12.25,16.83) 236(-12.75,16.83) 237(-13.25,16.83) 238(-13.75,16.83) 239(-14.25,16.83) 240(-14.75,16.83)
Top Overlay:
  circle w0.25: c-16.83,15.45 r0.125
  lines w0.2: -15.525,-15.525 15.525,-15.525 15.525,15.525 -15.525,15.525 -15.525,-15.525

## F-QFP32x32-G240/Y1.4N [mm]
pads (240):
  rect 1.4x0.3 smd: 1(-17,14.75) 2(-17,14.25) 3(-17,13.75) 4(-17,13.25) 5(-17,12.75) 6(-17,12.25) 7(-17,11.75) 8(-17,11.25) 9(-17,10.75) 10(-17,10.25) 11(-17,9.75) 12(-17,9.25) 13(-17,8.75) 14(-17,8.25) 15(-17,7.75) 16(-17,7.25) 17(-17,6.75) 18(-17,6.25) 19(-17,5.75) 20(-17,5.25) 21(-17,4.75) 22(-17,4.25) 23(-17,3.75) 24(-17,3.25) 25(-17,2.75) 26(-17,2.25) 27(-17,1.75) 28(-17,1.25) 29(-17,0.75) 30(-17,0.25) 31(-17,-0.25) 32(-17,-0.75) 33(-17,-1.25) 34(-17,-1.75) 35(-17,-2.25) 36(-17,-2.75) 37(-17,-3.25) 38(-17,-3.75) 39(-17,-4.25) 40(-17,-4.75) 41(-17,-5.25) 42(-17,-5.75) 43(-17,-6.25) 44(-17,-6.75) 45(-17,-7.25) 46(-17,-7.75) 47(-17,-8.25) 48(-17,-8.75) 49(-17,-9.25) 50(-17,-9.75) 51(-17,-10.25) 52(-17,-10.75) 53(-17,-11.25) 54(-17,-11.75) 55(-17,-12.25) 56(-17,-12.75) 57(-17,-13.25) 58(-17,-13.75) 59(-17,-14.25) 60(-17,-14.75) 121(17,-14.75) 122(17,-14.25) 123(17,-13.75) 124(17,-13.25) 125(17,-12.75) 126(17,-12.25) 127(17,-11.75) 128(17,-11.25) 129(17,-10.75) 130(17,-10.25) 131(17,-9.75) 132(17,-9.25) 133(17,-8.75) 134(17,-8.25) 135(17,-7.75) 136(17,-7.25) 137(17,-6.75) 138(17,-6.25) 139(17,-5.75) 140(17,-5.25) 141(17,-4.75) 142(17,-4.25) 143(17,-3.75) 144(17,-3.25) 145(17,-2.75) 146(17,-2.25) 147(17,-1.75) 148(17,-1.25) 149(17,-0.75) 150(17,-0.25) 151(17,0.25) 152(17,0.75) 153(17,1.25) 154(17,1.75) 155(17,2.25) 156(17,2.75) 157(17,3.25) 158(17,3.75) 159(17,4.25) 160(17,4.75) 161(17,5.25) 162(17,5.75) 163(17,6.25) 164(17,6.75) 165(17,7.25) 166(17,7.75) 167(17,8.25) 168(17,8.75) 169(17,9.25) 170(17,9.75) 171(17,10.25) 172(17,10.75) 173(17,11.25) 174(17,11.75) 175(17,12.25) 176(17,12.75) 177(17,13.25) 178(17,13.75) 179(17,14.25) 180(17,14.75)
  rect 0.3x1.4 smd: 61(-14.75,-17) 62(-14.25,-17) 63(-13.75,-17) 64(-13.25,-17) 65(-12.75,-17) 66(-12.25,-17) 67(-11.75,-17) 68(-11.25,-17) 69(-10.75,-17) 70(-10.25,-17) 71(-9.75,-17) 72(-9.25,-17) 73(-8.75,-17) 74(-8.25,-17) 75(-7.75,-17) 76(-7.25,-17) 77(-6.75,-17) 78(-6.25,-17) 79(-5.75,-17) 80(-5.25,-17) 81(-4.75,-17) 82(-4.25,-17) 83(-3.75,-17) 84(-3.25,-17) 85(-2.75,-17) 86(-2.25,-17) 87(-1.75,-17) 88(-1.25,-17) 89(-0.75,-17) 90(-0.25,-17) 91(0.25,-17) 92(0.75,-17) 93(1.25,-17) 94(1.75,-17) 95(2.25,-17) 96(2.75,-17) 97(3.25,-17) 98(3.75,-17) 99(4.25,-17) 100(4.75,-17) 101(5.25,-17) 102(5.75,-17) 103(6.25,-17) 104(6.75,-17) 105(7.25,-17) 106(7.75,-17) 107(8.25,-17) 108(8.75,-17) 109(9.25,-17) 110(9.75,-17) 111(10.25,-17) 112(10.75,-17) 113(11.25,-17) 114(11.75,-17) 115(12.25,-17) 116(12.75,-17) 117(13.25,-17) 118(13.75,-17) 119(14.25,-17) 120(14.75,-17) 181(14.75,17) 182(14.25,17) 183(13.75,17) 184(13.25,17) 185(12.75,17) 186(12.25,17) 187(11.75,17) 188(11.25,17) 189(10.75,17) 190(10.25,17) 191(9.75,17) 192(9.25,17) 193(8.75,17) 194(8.25,17) 195(7.75,17) 196(7.25,17) 197(6.75,17) 198(6.25,17) 199(5.75,17) 200(5.25,17) 201(4.75,17) 202(4.25,17) 203(3.75,17) 204(3.25,17) 205(2.75,17) 206(2.25,17) 207(1.75,17) 208(1.25,17) 209(0.75,17) 210(0.25,17) 211(-0.25,17) 212(-0.75,17) 213(-1.25,17) 214(-1.75,17) 215(-2.25,17) 216(-2.75,17) 217(-3.25,17) 218(-3.75,17) 219(-4.25,17) 220(-4.75,17) 221(-5.25,17) 222(-5.75,17) 223(-6.25,17) 224(-6.75,17) 225(-7.25,17) 226(-7.75,17) 227(-8.25,17) 228(-8.75,17) 229(-9.25,17) 230(-9.75,17) 231(-10.25,17) 232(-10.75,17) 233(-11.25,17) 234(-11.75,17) 235(-12.25,17) 236(-12.75,17) 237(-13.25,17) 238(-13.75,17) 239(-14.25,17) 240(-14.75,17)
Top Overlay:
  circle w0.25: c-17,15.45 r0.125
  lines w0.2: -15.9,-15.9 15.9,-15.9 15.9,15.9 -15.9,15.9 -15.9,-15.9

## F-QFP32X32-G240/Y1.5N [mm]
pads (240):
  rect 1.5x0.3 smd: 1(-16.975,14.75) 2(-16.975,14.25) 3(-16.975,13.75) 4(-16.975,13.25) 5(-16.975,12.75) 6(-16.975,12.25) 7(-16.975,11.75) 8(-16.975,11.25) 9(-16.975,10.75) 10(-16.975,10.25) 11(-16.975,9.75) 12(-16.975,9.25) 13(-16.975,8.75) 14(-16.975,8.25) 15(-16.975,7.75) 16(-16.975,7.25) 17(-16.975,6.75) 18(-16.975,6.25) 19(-16.975,5.75) 20(-16.975,5.25) 21(-16.975,4.75) 22(-16.975,4.25) 23(-16.975,3.75) 24(-16.975,3.25) 25(-16.975,2.75) 26(-16.975,2.25) 27(-16.975,1.75) 28(-16.975,1.25) 29(-16.975,0.75) 30(-16.975,0.25) 31(-16.975,-0.25) 32(-16.975,-0.75) 33(-16.975,-1.25) 34(-16.975,-1.75) 35(-16.975,-2.25) 36(-16.975,-2.75) 37(-16.975,-3.25) 38(-16.975,-3.75) 39(-16.975,-4.25) 40(-16.975,-4.75) 41(-16.975,-5.25) 42(-16.975,-5.75) 43(-16.975,-6.25) 44(-16.975,-6.75) 45(-16.975,-7.25) 46(-16.975,-7.75) 47(-16.975,-8.25) 48(-16.975,-8.75) 49(-16.975,-9.25) 50(-16.975,-9.75) 51(-16.975,-10.25) 52(-16.975,-10.75) 53(-16.975,-11.25) 54(-16.975,-11.75) 55(-16.975,-12.25) 56(-16.975,-12.75) 57(-16.975,-13.25) 58(-16.975,-13.75) 59(-16.975,-14.25) 60(-16.975,-14.75) 121(16.975,-14.75) 122(16.975,-14.25) 123(16.975,-13.75) 124(16.975,-13.25) 125(16.975,-12.75) 126(16.975,-12.25) 127(16.975,-11.75) 128(16.975,-11.25) 129(16.975,-10.75) 130(16.975,-10.25) 131(16.975,-9.75) 132(16.975,-9.25) 133(16.975,-8.75) 134(16.975,-8.25) 135(16.975,-7.75) 136(16.975,-7.25) 137(16.975,-6.75) 138(16.975,-6.25) 139(16.975,-5.75) 140(16.975,-5.25) 141(16.975,-4.75) 142(16.975,-4.25) 143(16.975,-3.75) 144(16.975,-3.25) 145(16.975,-2.75) 146(16.975,-2.25) 147(16.975,-1.75) 148(16.975,-1.25) 149(16.975,-0.75) 150(16.975,-0.25) 151(16.975,0.25) 152(16.975,0.75) 153(16.975,1.25) 154(16.975,1.75) 155(16.975,2.25) 156(16.975,2.75) 157(16.975,3.25) 158(16.975,3.75) 159(16.975,4.25) 160(16.975,4.75) 161(16.975,5.25) 162(16.975,5.75) 163(16.975,6.25) 164(16.975,6.75) 165(16.975,7.25) 166(16.975,7.75) 167(16.975,8.25) 168(16.975,8.75) 169(16.975,9.25) 170(16.975,9.75) 171(16.975,10.25) 172(16.975,10.75) 173(16.975,11.25) 174(16.975,11.75) 175(16.975,12.25) 176(16.975,12.75) 177(16.975,13.25) 178(16.975,13.75) 179(16.975,14.25) 180(16.975,14.75)
  rect 0.3x1.5 smd: 61(-14.75,-16.975) 62(-14.25,-16.975) 63(-13.75,-16.975) 64(-13.25,-16.975) 65(-12.75,-16.975) 66(-12.25,-16.975) 67(-11.75,-16.975) 68(-11.25,-16.975) 69(-10.75,-16.975) 70(-10.25,-16.975) 71(-9.75,-16.975) 72(-9.25,-16.975) 73(-8.75,-16.975) 74(-8.25,-16.975) 75(-7.75,-16.975) 76(-7.25,-16.975) 77(-6.75,-16.975) 78(-6.25,-16.975) 79(-5.75,-16.975) 80(-5.25,-16.975) 81(-4.75,-16.975) 82(-4.25,-16.975) 83(-3.75,-16.975) 84(-3.25,-16.975) 85(-2.75,-16.975) 86(-2.25,-16.975) 87(-1.75,-16.975) 88(-1.25,-16.975) 89(-0.75,-16.975) 90(-0.25,-16.975) 91(0.25,-16.975) 92(0.75,-16.975) 93(1.25,-16.975) 94(1.75,-16.975) 95(2.25,-16.975) 96(2.75,-16.975) 97(3.25,-16.975) 98(3.75,-16.975) 99(4.25,-16.975) 100(4.75,-16.975) 101(5.25,-16.975) 102(5.75,-16.975) 103(6.25,-16.975) 104(6.75,-16.975) 105(7.25,-16.975) 106(7.75,-16.975) 107(8.25,-16.975) 108(8.75,-16.975) 109(9.25,-16.975) 110(9.75,-16.975) 111(10.25,-16.975) 112(10.75,-16.975) 113(11.25,-16.975) 114(11.75,-16.975) 115(12.25,-16.975) 116(12.75,-16.975) 117(13.25,-16.975) 118(13.75,-16.975) 119(14.25,-16.975) 120(14.75,-16.975) 181(14.75,16.975) 182(14.25,16.975) 183(13.75,16.975) 184(13.25,16.975) 185(12.75,16.975) 186(12.25,16.975) 187(11.75,16.975) 188(11.25,16.975) 189(10.75,16.975) 190(10.25,16.975) 191(9.75,16.975) 192(9.25,16.975) 193(8.75,16.975) 194(8.25,16.975) 195(7.75,16.975) 196(7.25,16.975) 197(6.75,16.975) 198(6.25,16.975) 199(5.75,16.975) 200(5.25,16.975) 201(4.75,16.975) 202(4.25,16.975) 203(3.75,16.975) 204(3.25,16.975) 205(2.75,16.975) 206(2.25,16.975) 207(1.75,16.975) 208(1.25,16.975) 209(0.75,16.975) 210(0.25,16.975) 211(-0.25,16.975) 212(-0.75,16.975) 213(-1.25,16.975) 214(-1.75,16.975) 215(-2.25,16.975) 216(-2.75,16.975) 217(-3.25,16.975) 218(-3.75,16.975) 219(-4.25,16.975) 220(-4.75,16.975) 221(-5.25,16.975) 222(-5.75,16.975) 223(-6.25,16.975) 224(-6.75,16.975) 225(-7.25,16.975) 226(-7.75,16.975) 227(-8.25,16.975) 228(-8.75,16.975) 229(-9.25,16.975) 230(-9.75,16.975) 231(-10.25,16.975) 232(-10.75,16.975) 233(-11.25,16.975) 234(-11.75,16.975) 235(-12.25,16.975) 236(-12.75,16.975) 237(-13.25,16.975) 238(-13.75,16.975) 239(-14.25,16.975) 240(-14.75,16.975)
Top Overlay:
  circle w0.25: c-16.975,15.45 r0.125
  lines w0.2: -15.825,-15.825 15.825,-15.825 15.825,15.825 -15.825,15.825 -15.825,-15.825

## F-QFP32X32-G240/Y1.6N [mm]
pads (240):
  rect 1.6x0.3 smd: 1(-16.925,14.75) 2(-16.925,14.25) 3(-16.925,13.75) 4(-16.925,13.25) 5(-16.925,12.75) 6(-16.925,12.25) 7(-16.925,11.75) 8(-16.925,11.25) 9(-16.925,10.75) 10(-16.925,10.25) 11(-16.925,9.75) 12(-16.925,9.25) 13(-16.925,8.75) 14(-16.925,8.25) 15(-16.925,7.75) 16(-16.925,7.25) 17(-16.925,6.75) 18(-16.925,6.25) 19(-16.925,5.75) 20(-16.925,5.25) 21(-16.925,4.75) 22(-16.925,4.25) 23(-16.925,3.75) 24(-16.925,3.25) 25(-16.925,2.75) 26(-16.925,2.25) 27(-16.925,1.75) 28(-16.925,1.25) 29(-16.925,0.75) 30(-16.925,0.25) 31(-16.925,-0.25) 32(-16.925,-0.75) 33(-16.925,-1.25) 34(-16.925,-1.75) 35(-16.925,-2.25) 36(-16.925,-2.75) 37(-16.925,-3.25) 38(-16.925,-3.75) 39(-16.925,-4.25) 40(-16.925,-4.75) 41(-16.925,-5.25) 42(-16.925,-5.75) 43(-16.925,-6.25) 44(-16.925,-6.75) 45(-16.925,-7.25) 46(-16.925,-7.75) 47(-16.925,-8.25) 48(-16.925,-8.75) 49(-16.925,-9.25) 50(-16.925,-9.75) 51(-16.925,-10.25) 52(-16.925,-10.75) 53(-16.925,-11.25) 54(-16.925,-11.75) 55(-16.925,-12.25) 56(-16.925,-12.75) 57(-16.925,-13.25) 58(-16.925,-13.75) 59(-16.925,-14.25) 60(-16.925,-14.75) 121(16.925,-14.75) 122(16.925,-14.25) 123(16.925,-13.75) 124(16.925,-13.25) 125(16.925,-12.75) 126(16.925,-12.25) 127(16.925,-11.75) 128(16.925,-11.25) 129(16.925,-10.75) 130(16.925,-10.25) 131(16.925,-9.75) 132(16.925,-9.25) 133(16.925,-8.75) 134(16.925,-8.25) 135(16.925,-7.75) 136(16.925,-7.25) 137(16.925,-6.75) 138(16.925,-6.25) 139(16.925,-5.75) 140(16.925,-5.25) 141(16.925,-4.75) 142(16.925,-4.25) 143(16.925,-3.75) 144(16.925,-3.25) 145(16.925,-2.75) 146(16.925,-2.25) 147(16.925,-1.75) 148(16.925,-1.25) 149(16.925,-0.75) 150(16.925,-0.25) 151(16.925,0.25) 152(16.925,0.75) 153(16.925,1.25) 154(16.925,1.75) 155(16.925,2.25) 156(16.925,2.75) 157(16.925,3.25) 158(16.925,3.75) 159(16.925,4.25) 160(16.925,4.75) 161(16.925,5.25) 162(16.925,5.75) 163(16.925,6.25) 164(16.925,6.75) 165(16.925,7.25) 166(16.925,7.75) 167(16.925,8.25) 168(16.925,8.75) 169(16.925,9.25) 170(16.925,9.75) 171(16.925,10.25) 172(16.925,10.75) 173(16.925,11.25) 174(16.925,11.75) 175(16.925,12.25) 176(16.925,12.75) 177(16.925,13.25) 178(16.925,13.75) 179(16.925,14.25) 180(16.925,14.75)
  rect 0.3x1.6 smd: 61(-14.75,-16.925) 62(-14.25,-16.925) 63(-13.75,-16.925) 64(-13.25,-16.925) 65(-12.75,-16.925) 66(-12.25,-16.925) 67(-11.75,-16.925) 68(-11.25,-16.925) 69(-10.75,-16.925) 70(-10.25,-16.925) 71(-9.75,-16.925) 72(-9.25,-16.925) 73(-8.75,-16.925) 74(-8.25,-16.925) 75(-7.75,-16.925) 76(-7.25,-16.925) 77(-6.75,-16.925) 78(-6.25,-16.925) 79(-5.75,-16.925) 80(-5.25,-16.925) 81(-4.75,-16.925) 82(-4.25,-16.925) 83(-3.75,-16.925) 84(-3.25,-16.925) 85(-2.75,-16.925) 86(-2.25,-16.925) 87(-1.75,-16.925) 88(-1.25,-16.925) 89(-0.75,-16.925) 90(-0.25,-16.925) 91(0.25,-16.925) 92(0.75,-16.925) 93(1.25,-16.925) 94(1.75,-16.925) 95(2.25,-16.925) 96(2.75,-16.925) 97(3.25,-16.925) 98(3.75,-16.925) 99(4.25,-16.925) 100(4.75,-16.925) 101(5.25,-16.925) 102(5.75,-16.925) 103(6.25,-16.925) 104(6.75,-16.925) 105(7.25,-16.925) 106(7.75,-16.925) 107(8.25,-16.925) 108(8.75,-16.925) 109(9.25,-16.925) 110(9.75,-16.925) 111(10.25,-16.925) 112(10.75,-16.925) 113(11.25,-16.925) 114(11.75,-16.925) 115(12.25,-16.925) 116(12.75,-16.925) 117(13.25,-16.925) 118(13.75,-16.925) 119(14.25,-16.925) 120(14.75,-16.925) 181(14.75,16.925) 182(14.25,16.925) 183(13.75,16.925) 184(13.25,16.925) 185(12.75,16.925) 186(12.25,16.925) 187(11.75,16.925) 188(11.25,16.925) 189(10.75,16.925) 190(10.25,16.925) 191(9.75,16.925) 192(9.25,16.925) 193(8.75,16.925) 194(8.25,16.925) 195(7.75,16.925) 196(7.25,16.925) 197(6.75,16.925) 198(6.25,16.925) 199(5.75,16.925) 200(5.25,16.925) 201(4.75,16.925) 202(4.25,16.925) 203(3.75,16.925) 204(3.25,16.925) 205(2.75,16.925) 206(2.25,16.925) 207(1.75,16.925) 208(1.25,16.925) 209(0.75,16.925) 210(0.25,16.925) 211(-0.25,16.925) 212(-0.75,16.925) 213(-1.25,16.925) 214(-1.75,16.925) 215(-2.25,16.925) 216(-2.75,16.925) 217(-3.25,16.925) 218(-3.75,16.925) 219(-4.25,16.925) 220(-4.75,16.925) 221(-5.25,16.925) 222(-5.75,16.925) 223(-6.25,16.925) 224(-6.75,16.925) 225(-7.25,16.925) 226(-7.75,16.925) 227(-8.25,16.925) 228(-8.75,16.925) 229(-9.25,16.925) 230(-9.75,16.925) 231(-10.25,16.925) 232(-10.75,16.925) 233(-11.25,16.925) 234(-11.75,16.925) 235(-12.25,16.925) 236(-12.75,16.925) 237(-13.25,16.925) 238(-13.75,16.925) 239(-14.25,16.925) 240(-14.75,16.925)
Top Overlay:
  circle w0.25: c-16.925,15.45 r0.125
  lines w0.2: -15.725,-15.725 -15.725,15.725 15.725,15.725 15.725,-15.725 -15.725,-15.725

## F-QFP32X32-G248/N [mm]
pads (248):
  rect 1.6x0.3 smd: 1(-16.6,15.25) 2(-16.6,14.75) 3(-16.6,14.25) 4(-16.6,13.75) 5(-16.6,13.25) 6(-16.6,12.75) 7(-16.6,12.25) 8(-16.6,11.75) 9(-16.6,11.25) 10(-16.6,10.75) 11(-16.6,10.25) 12(-16.6,9.75) 13(-16.6,9.25) 14(-16.6,8.75) 15(-16.6,8.25) 16(-16.6,7.75) 17(-16.6,7.25) 18(-16.6,6.75) 19(-16.6,6.25) 20(-16.6,5.75) 21(-16.6,5.25) 22(-16.6,4.75) 23(-16.6,4.25) 24(-16.6,3.75) 25(-16.6,3.25) 26(-16.6,2.75) 27(-16.6,2.25) 28(-16.6,1.75) 29(-16.6,1.25) 30(-16.6,0.75) 31(-16.6,0.25) 32(-16.6,-0.25) 33(-16.6,-0.75) 34(-16.6,-1.25) 35(-16.6,-1.75) 36(-16.6,-2.25) 37(-16.6,-2.75) 38(-16.6,-3.25) 39(-16.6,-3.75) 40(-16.6,-4.25) 41(-16.6,-4.75) 42(-16.6,-5.25) 43(-16.6,-5.75) 44(-16.6,-6.25) 45(-16.6,-6.75) 46(-16.6,-7.25) 47(-16.6,-7.75) 48(-16.6,-8.25) 49(-16.6,-8.75) 50(-16.6,-9.25) 51(-16.6,-9.75) 52(-16.6,-10.25) 53(-16.6,-10.75) 54(-16.6,-11.25) 55(-16.6,-11.75) 56(-16.6,-12.25) 57(-16.6,-12.75) 58(-16.6,-13.25) 59(-16.6,-13.75) 60(-16.6,-14.25) 61(-16.6,-14.75) 62(-16.6,-15.25) 125(16.6,-15.25) 126(16.6,-14.75) 127(16.6,-14.25) 128(16.6,-13.75) 129(16.6,-13.25) 130(16.6,-12.75) 131(16.6,-12.25) 132(16.6,-11.75) 133(16.6,-11.25) 134(16.6,-10.75) 135(16.6,-10.25) 136(16.6,-9.75) 137(16.6,-9.25) 138(16.6,-8.75) 139(16.6,-8.25) 140(16.6,-7.75) 141(16.6,-7.25) 142(16.6,-6.75) 143(16.6,-6.25) 144(16.6,-5.75) 145(16.6,-5.25) 146(16.6,-4.75) 147(16.6,-4.25) 148(16.6,-3.75) 149(16.6,-3.25) 150(16.6,-2.75) 151(16.6,-2.25) 152(16.6,-1.75) 153(16.6,-1.25) 154(16.6,-0.75) 155(16.6,-0.25) 156(16.6,0.25) 157(16.6,0.75) 158(16.6,1.25) 159(16.6,1.75) 160(16.6,2.25) 161(16.6,2.75) 162(16.6,3.25) 163(16.6,3.75) 164(16.6,4.25) 165(16.6,4.75) 166(16.6,5.25) 167(16.6,5.75) 168(16.6,6.25) 169(16.6,6.75) 170(16.6,7.25) 171(16.6,7.75) 172(16.6,8.25) 173(16.6,8.75) 174(16.6,9.25) 175(16.6,9.75) 176(16.6,10.25) 177(16.6,10.75) 178(16.6,11.25) 179(16.6,11.75) 180(16.6,12.25) 181(16.6,12.75) 182(16.6,13.25) 183(16.6,13.75) 184(16.6,14.25) 185(16.6,14.75) 186(16.6,15.25)
  rect 0.3x1.6 smd: 63(-15.25,-16.6) 64(-14.75,-16.6) 65(-14.25,-16.6) 66(-13.75,-16.6) 67(-13.25,-16.6) 68(-12.75,-16.6) 69(-12.25,-16.6) 70(-11.75,-16.6) 71(-11.25,-16.6) 72(-10.75,-16.6) 73(-10.25,-16.6) 74(-9.75,-16.6) 75(-9.25,-16.6) 76(-8.75,-16.6) 77(-8.25,-16.6) 78(-7.75,-16.6) 79(-7.25,-16.6) 80(-6.75,-16.6) 81(-6.25,-16.6) 82(-5.75,-16.6) 83(-5.25,-16.6) 84(-4.75,-16.6) 85(-4.25,-16.6) 86(-3.75,-16.6) 87(-3.25,-16.6) 88(-2.75,-16.6) 89(-2.25,-16.6) 90(-1.75,-16.6) 91(-1.25,-16.6) 92(-0.75,-16.6) 93(-0.25,-16.6) 94(0.25,-16.6) 95(0.75,-16.6) 96(1.25,-16.6) 97(1.75,-16.6) 98(2.25,-16.6) 99(2.75,-16.6) 100(3.25,-16.6) 101(3.75,-16.6) 102(4.25,-16.6) 103(4.75,-16.6) 104(5.25,-16.6) 105(5.75,-16.6) 106(6.25,-16.6) 107(6.75,-16.6) 108(7.25,-16.6) 109(7.75,-16.6) 110(8.25,-16.6) 111(8.75,-16.6) 112(9.25,-16.6) 113(9.75,-16.6) 114(10.25,-16.6) 115(10.75,-16.6) 116(11.25,-16.6) 117(11.75,-16.6) 118(12.25,-16.6) 119(12.75,-16.6) 120(13.25,-16.6) 121(13.75,-16.6) 122(14.25,-16.6) 123(14.75,-16.6) 124(15.25,-16.6) 187(15.25,16.6) 188(14.75,16.6) 189(14.25,16.6) 190(13.75,16.6) 191(13.25,16.6) 192(12.75,16.6) 193(12.25,16.6) 194(11.75,16.6) 195(11.25,16.6) 196(10.75,16.6) 197(10.25,16.6) 198(9.75,16.6) 199(9.25,16.6) 200(8.75,16.6) 201(8.25,16.6) 202(7.75,16.6) 203(7.25,16.6) 204(6.75,16.6) 205(6.25,16.6) 206(5.75,16.6) 207(5.25,16.6) 208(4.75,16.6) 209(4.25,16.6) 210(3.75,16.6) 211(3.25,16.6) 212(2.75,16.6) 213(2.25,16.6) 214(1.75,16.6) 215(1.25,16.6) 216(0.75,16.6) 217(0.25,16.6) 218(-0.25,16.6) 219(-0.75,16.6) 220(-1.25,16.6) 221(-1.75,16.6) 222(-2.25,16.6) 223(-2.75,16.6) 224(-3.25,16.6) 225(-3.75,16.6) 226(-4.25,16.6) 227(-4.75,16.6) 228(-5.25,16.6) 229(-5.75,16.6) 230(-6.25,16.6) 231(-6.75,16.6) 232(-7.25,16.6) 233(-7.75,16.6) 234(-8.25,16.6) 235(-8.75,16.6) 236(-9.25,16.6) 237(-9.75,16.6) 238(-10.25,16.6) 239(-10.75,16.6) 240(-11.25,16.6) 241(-11.75,16.6) 242(-12.25,16.6) 243(-12.75,16.6) 244(-13.25,16.6) 245(-13.75,16.6) 246(-14.25,16.6) 247(-14.75,16.6) 248(-15.25,16.6)
Top Overlay:
  circle w0.25: c-17.96,15.25 r0.125
  lines w0.2: -15.4,-15.4 -15.4,15.4 15.4,15.4 15.4,-15.4 -15.4,-15.4

## F-QFP36X36-G272/N [mm]
pads (272):
  rect 1.6x0.3 smd: 1(-18.6,16.75) 2(-18.6,16.25) 3(-18.6,15.75) 4(-18.6,15.25) 5(-18.6,14.75) 6(-18.6,14.25) 7(-18.6,13.75) 8(-18.6,13.25) 9(-18.6,12.75) 10(-18.6,12.25) 11(-18.6,11.75) 12(-18.6,11.25) 13(-18.6,10.75) 14(-18.6,10.25) 15(-18.6,9.75) 16(-18.6,9.25) 17(-18.6,8.75) 18(-18.6,8.25) 19(-18.6,7.75) 20(-18.6,7.25) 21(-18.6,6.75) 22(-18.6,6.25) 23(-18.6,5.75) 24(-18.6,5.25) 25(-18.6,4.75) 26(-18.6,4.25) 27(-18.6,3.75) 28(-18.6,3.25) 29(-18.6,2.75) 30(-18.6,2.25) 31(-18.6,1.75) 32(-18.6,1.25) 33(-18.6,0.75) 34(-18.6,0.25) 35(-18.6,-0.25) 36(-18.6,-0.75) 37(-18.6,-1.25) 38(-18.6,-1.75) 39(-18.6,-2.25) 40(-18.6,-2.75) 41(-18.6,-3.25) 42(-18.6,-3.75) 43(-18.6,-4.25) 44(-18.6,-4.75) 45(-18.6,-5.25) 46(-18.6,-5.75) 47(-18.6,-6.25) 48(-18.6,-6.75) 49(-18.6,-7.25) 50(-18.6,-7.75) 51(-18.6,-8.25) 52(-18.6,-8.75) 53(-18.6,-9.25) 54(-18.6,-9.75) 55(-18.6,-10.25) 56(-18.6,-10.75) 57(-18.6,-11.25) 58(-18.6,-11.75) 59(-18.6,-12.25) 60(-18.6,-12.75) 61(-18.6,-13.25) 62(-18.6,-13.75) 63(-18.6,-14.25) 64(-18.6,-14.75) 65(-18.6,-15.25) 66(-18.6,-15.75) 67(-18.6,-16.25) 68(-18.6,-16.75) 137(18.6,-16.75) 138(18.6,-16.25) 139(18.6,-15.75) 140(18.6,-15.25) 141(18.6,-14.75) 142(18.6,-14.25) 143(18.6,-13.75) 144(18.6,-13.25) 145(18.6,-12.75) 146(18.6,-12.25) 147(18.6,-11.75) 148(18.6,-11.25) 149(18.6,-10.75) 150(18.6,-10.25) 151(18.6,-9.75) 152(18.6,-9.25) 153(18.6,-8.75) 154(18.6,-8.25) 155(18.6,-7.75) 156(18.6,-7.25) 157(18.6,-6.75) 158(18.6,-6.25) 159(18.6,-5.75) 160(18.6,-5.25) 161(18.6,-4.75) 162(18.6,-4.25) 163(18.6,-3.75) 164(18.6,-3.25) 165(18.6,-2.75) 166(18.6,-2.25) 167(18.6,-1.75) 168(18.6,-1.25) 169(18.6,-0.75) 170(18.6,-0.25) 171(18.6,0.25) 172(18.6,0.75) 173(18.6,1.25) 174(18.6,1.75) 175(18.6,2.25) 176(18.6,2.75) 177(18.6,3.25) 178(18.6,3.75) 179(18.6,4.25) 180(18.6,4.75) 181(18.6,5.25) 182(18.6,5.75) 183(18.6,6.25) 184(18.6,6.75) 185(18.6,7.25) 186(18.6,7.75) 187(18.6,8.25) 188(18.6,8.75) 189(18.6,9.25) 190(18.6,9.75) 191(18.6,10.25) 192(18.6,10.75) 193(18.6,11.25) 194(18.6,11.75) 195(18.6,12.25) 196(18.6,12.75) 197(18.6,13.25) 198(18.6,13.75) 199(18.6,14.25) 200(18.6,14.75) 201(18.6,15.25) 202(18.6,15.75) 203(18.6,16.25) 204(18.6,16.75)
  rect 0.3x1.6 smd: 69(-16.75,-18.6) 70(-16.25,-18.6) 71(-15.75,-18.6) 72(-15.25,-18.6) 73(-14.75,-18.6) 74(-14.25,-18.6) 75(-13.75,-18.6) 76(-13.25,-18.6) 77(-12.75,-18.6) 78(-12.25,-18.6) 79(-11.75,-18.6) 80(-11.25,-18.6) 81(-10.75,-18.6) 82(-10.25,-18.6) 83(-9.75,-18.6) 84(-9.25,-18.6) 85(-8.75,-18.6) 86(-8.25,-18.6) 87(-7.75,-18.6) 88(-7.25,-18.6) 89(-6.75,-18.6) 90(-6.25,-18.6) 91(-5.75,-18.6) 92(-5.25,-18.6) 93(-4.75,-18.6) 94(-4.25,-18.6) 95(-3.75,-18.6) 96(-3.25,-18.6) 97(-2.75,-18.6) 98(-2.25,-18.6) 99(-1.75,-18.6) 100(-1.25,-18.6) 101(-0.75,-18.6) 102(-0.25,-18.6) 103(0.25,-18.6) 104(0.75,-18.6) 105(1.25,-18.6) 106(1.75,-18.6) 107(2.25,-18.6) 108(2.75,-18.6) 109(3.25,-18.6) 110(3.75,-18.6) 111(4.25,-18.6) 112(4.75,-18.6) 113(5.25,-18.6) 114(5.75,-18.6) 115(6.25,-18.6) 116(6.75,-18.6) 117(7.25,-18.6) 118(7.75,-18.6) 119(8.25,-18.6) 120(8.75,-18.6) 121(9.25,-18.6) 122(9.75,-18.6) 123(10.25,-18.6) 124(10.75,-18.6) 125(11.25,-18.6) 126(11.75,-18.6) 127(12.25,-18.6) 128(12.75,-18.6) 129(13.25,-18.6) 130(13.75,-18.6) 131(14.25,-18.6) 132(14.75,-18.6) 133(15.25,-18.6) 134(15.75,-18.6) 135(16.25,-18.6) 136(16.75,-18.6) 205(16.75,18.6) 206(16.25,18.6) 207(15.75,18.6) 208(15.25,18.6) 209(14.75,18.6) 210(14.25,18.6) 211(13.75,18.6) 212(13.25,18.6) 213(12.75,18.6) 214(12.25,18.6) 215(11.75,18.6) 216(11.25,18.6) 217(10.75,18.6) 218(10.25,18.6) 219(9.75,18.6) 220(9.25,18.6) 221(8.75,18.6) 222(8.25,18.6) 223(7.75,18.6) 224(7.25,18.6) 225(6.75,18.6) 226(6.25,18.6) 227(5.75,18.6) 228(5.25,18.6) 229(4.75,18.6) 230(4.25,18.6) 231(3.75,18.6) 232(3.25,18.6) 233(2.75,18.6) 234(2.25,18.6) 235(1.75,18.6) 236(1.25,18.6) 237(0.75,18.6) 238(0.25,18.6) 239(-0.25,18.6) 240(-0.75,18.6) 241(-1.25,18.6) 242(-1.75,18.6) 243(-2.25,18.6) 244(-2.75,18.6) 245(-3.25,18.6) 246(-3.75,18.6) 247(-4.25,18.6) 248(-4.75,18.6) 249(-5.25,18.6) 250(-5.75,18.6) 251(-6.25,18.6) 252(-6.75,18.6) 253(-7.25,18.6) 254(-7.75,18.6) 255(-8.25,18.6) 256(-8.75,18.6) 257(-9.25,18.6) 258(-9.75,18.6) 259(-10.25,18.6) 260(-10.75,18.6) 261(-11.25,18.6) 262(-11.75,18.6) 263(-12.25,18.6) 264(-12.75,18.6) 265(-13.25,18.6) 266(-13.75,18.6) 267(-14.25,18.6) 268(-14.75,18.6) 269(-15.25,18.6) 270(-15.75,18.6) 271(-16.25,18.6) 272(-16.75,18.6)
Top Overlay:
  circle w0.25: c-19.96,16.75 r0.125
  lines w0.2: -17.4,-17.4 17.4,-17.4 17.4,17.4 -17.4,17.4 -17.4,-17.4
